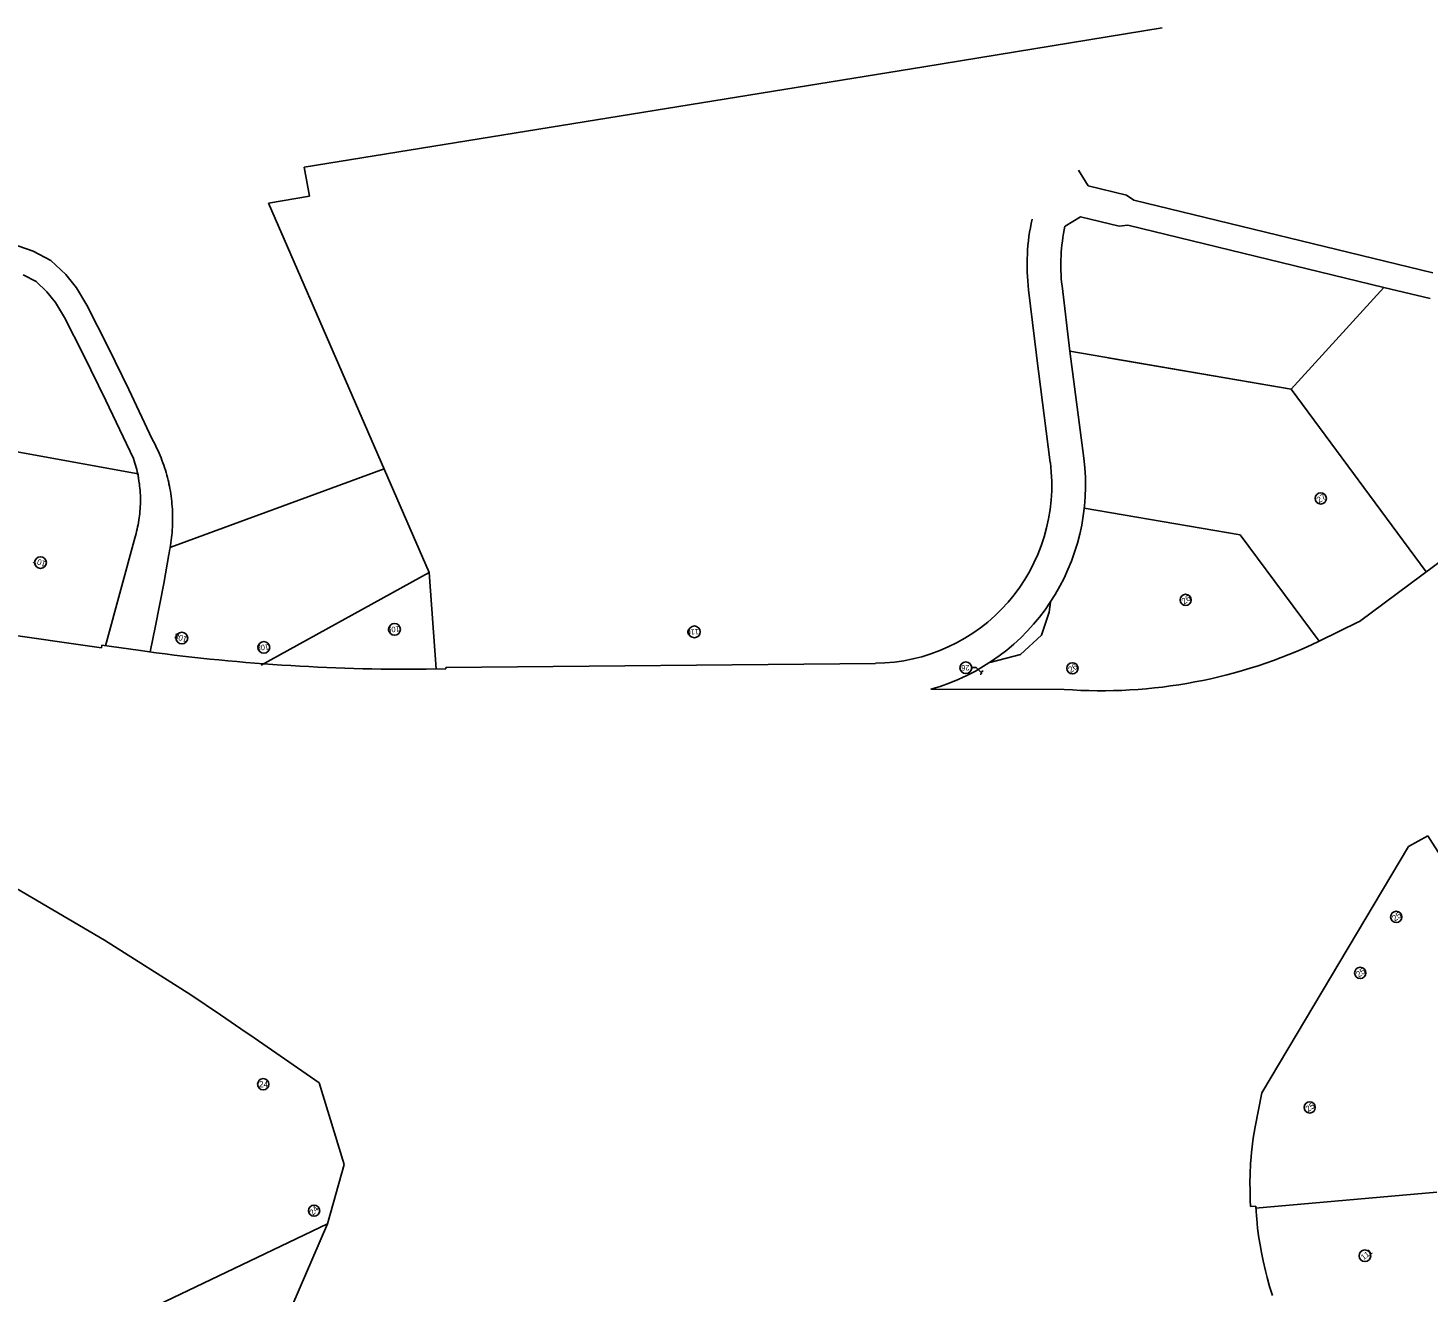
# Model space of a CAD drawing. Extents: x 1601085 to 1622464, y 1082944 to 1103437.
# Drawn here: x 1609043 to 1611786, y 1093415 to 1095892 of the extents above; entities that cross this region are included whole.
import ezdxf

# ---------------------------------------------------------------- set-up
doc = ezdxf.new("R2010")
doc.units = 0
for name, color, linetype in [('RD_EX_Bldg', 7, 'Continuous'), ('RD_EX_Fence_ChLk', 7, 'Continuous'), ('RD_EX_Fence_Other_txCode', 7, 'Continuous')]:
    doc.layers.add(name, color=color, linetype=linetype)

msp = doc.modelspace()

# ---------------------------------------------------------------- linework, layer by layer
at = {"layer": 'RD_EX_Bldg'}
for p, q in [((1611265, 1095892.2), (1610798, 1095816.2)), ((1610798, 1095816.2), (1609583.8, 1095619.4)), ((1609583.8, 1095619.4), (1609594, 1095562.3)), ((1609594, 1095562.3), (1609513.7, 1095549.1)), ((1609513.7, 1095549.1), (1609828.7, 1094825.3)), ((1611517.8, 1095184), (1611699.9, 1095383.8)), ((1611517.8, 1095184), (1611084.5, 1095258.7)), ((1611158.8, 1095245.9), (1611517.8, 1095184)), ((1611782.8, 1094826.5), (1611517.8, 1095184)), ((1608950.6, 1095073.9), (1609258.4, 1095018.5)), ((1609740.3, 1095028.3), (1609322.7, 1094874.7)), ((1609258.4, 1095018.5), (1609259.3, 1095007.2)), ((1611418.2, 1094898.6), (1611112.2, 1094951.4)), ((1611572.7, 1094690.3), (1611418.2, 1094898.6)), ((1609499.7, 1094643.2), (1609828.7, 1094825.3)), ((1609828.7, 1094825.3), (1609842.5, 1094635.9)), ((1611043.5, 1094747.3), (1611046.2, 1094767.1)), ((1611028.5, 1094702.2), (1611043.5, 1094747.3)), ((1610987.5, 1094664.5), (1611028.5, 1094702.2)), ((1610928, 1094649.2), (1610930.2, 1094649.3)), ((1610930.2, 1094649.3), (1610987.5, 1094664.5)), ((1611803.7, 1093610.9), (1611448.2, 1093579.2)), ((1609629.5, 1093548.3), (1609476.9, 1093475.5)), ((1609476.9, 1093475.5), (1609049.5, 1093271.6))]:
    msp.add_line(p, q, dxfattribs=at)
at = {"layer": 'RD_EX_Fence_ChLk'}
for p, q in [((1610892.5, 1094638.9), (1610900.5, 1094639)), ((1610900.5, 1094639), (1610911.4, 1094628.7))]:
    msp.add_line(p, q, dxfattribs=at)
for centre, radius in [((1611576, 1094970.1), 11), ((1609067.1, 1094844.5), 11.5), ((1611311.3, 1094771.4), 11), ((1609761, 1094713.6), 11.5), ((1609344.1, 1094696.4), 11.5), ((1610348.5, 1094708.7), 11.5), ((1609504.8, 1094678.2), 11.5), ((1610880.5, 1094638.3), 11.5), ((1611089.4, 1094637.3), 11), ((1611724, 1094150.1), 11), ((1611653.3, 1094040.3), 11), ((1609503.5, 1093822.1), 11), ((1611554.4, 1093776.6), 11), ((1609603.3, 1093574.3), 11), ((1611662.5, 1093485.9), 11.5)]:
    msp.add_circle(centre, radius, dxfattribs=at)
for centre, start, end in [((1610908.8, 1094628.4), 262.3337, 8.1916), ((1610913.9, 1094629.3), 82.3337, 188.1916)]:
    msp.add_arc(centre, 2.64, start, end, dxfattribs=at)
at = {"layer": 'RD_EX_Fence_Other_txCode'}
for p, q in [((1611651.7, 1094729.1), (1613041.3, 1095762)), ((1611120.3, 1095583.1), (1611101.6, 1095613.4)), ((1611195.6, 1095564.8), (1611120.3, 1095583.1)), ((1611209.7, 1095554.6), (1611195.6, 1095564.8)), ((1611795.7, 1095412), (1611209.7, 1095554.6)), ((1611105.4, 1095521.8), (1611074.9, 1095503.5)), ((1611180.7, 1095503.5), (1611105.4, 1095521.8)), ((1611197.9, 1095506), (1611180.7, 1095503.5)), ((1611699.9, 1095383.8), (1611197.9, 1095506)), ((1609053, 1095454.5), (1608977.9, 1095480.6)), ((1609087.6, 1095436.3), (1609053, 1095454.5)), ((1609116.6, 1095409.1), (1609087.6, 1095436.3)), ((1609033.1, 1095408.5), (1609058.4, 1095395.2)), ((1609137.7, 1095382.8), (1609116.6, 1095409.1)), ((1609058.4, 1095395.2), (1609079.8, 1095375.1)), ((1609157.9, 1095349.1), (1609137.7, 1095382.8)), ((1611019, 1095250.8), (1611003.6, 1095379)), ((1611084.5, 1095258.7), (1611069.1, 1095386.9)), ((1611699.9, 1095383.8), (1611790.4, 1095361.7)), ((1609079.8, 1095375.1), (1609096.5, 1095354.2)), ((1609096.5, 1095354.2), (1609114.1, 1095324.8)), ((1609114.1, 1095324.8), (1609151.5, 1095251.7)), ((1609200.3, 1095265.6), (1609157.9, 1095349.1)), ((1609151.5, 1095251.7), (1609195.4, 1095162.3)), ((1609240.5, 1095183.9), (1609200.3, 1095265.6)), ((1611046.1, 1095040.8), (1611019, 1095250.2)), ((1611111.6, 1095049.2), (1611084.5, 1095258.7)), ((1609195.4, 1095162.3), (1609249.4, 1095048.2)), ((1609286.1, 1095086.4), (1609240.5, 1095183.9)), ((1609252.5, 1094894.9), (1609194.8, 1094681.5)), ((1609308.8, 1094803.5), (1609318.4, 1094860.5)), ((1609292.4, 1094720.6), (1609308.8, 1094803.5)), ((1609282.3, 1094669.3), (1609292.4, 1094720.6)), ((1611650.3, 1094728.1), (1611572.7, 1094690.3)), ((1611651.7, 1094729.1), (1611650.3, 1094728.1)), ((1608893.4, 1094718.9), (1609186.6, 1094677.6)), ((1609186.6, 1094677.6), (1609187.3, 1094682.6)), ((1609187.3, 1094682.6), (1609258.6, 1094672.5)), ((1610703.3, 1094647), (1609861.5, 1094639)), ((1609861.5, 1094639), (1609861.5, 1094636)), ((1609861.5, 1094636), (1609822.9, 1094635.7)), ((1610811.6, 1094596.3), (1611073.4, 1094595.8)), ((1611786.2, 1094309), (1611748.2, 1094288)), ((1611748.2, 1094288), (1611460.9, 1093805.2)), ((1609020.4, 1094205.8), (1609192.7, 1094104.7)), ((1609192.7, 1094104.7), (1609361.6, 1093997.5)), ((1609361.6, 1093997.5), (1609419.8, 1093957.8)), ((1609419.8, 1093957.8), (1609470.3, 1093923.7)), ((1609470.3, 1093923.7), (1609477.3, 1093918.9)), ((1609477.3, 1093918.9), (1609613.3, 1093824.8)), ((1609613.3, 1093824.8), (1609662.5, 1093664.8)), ((1609662.5, 1093664.8), (1609629.5, 1093548.3)), ((1611438.6, 1093582.6), (1611448.6, 1093583)), ((1609629.5, 1093548.3), (1609542, 1093346.4))]:
    msp.add_line(p, q, dxfattribs=at)
for points in [[(1609286.1, 1095086.4), (1609288.5, 1095081.9), (1609290.9, 1095077.4), (1609293.1, 1095072.9), (1609295.3, 1095068.3), (1609297.5, 1095063.7), (1609299.5, 1095059), (1609301.5, 1095054.3), (1609303.4, 1095049.6), (1609305.2, 1095044.9), (1609307, 1095040.1), (1609308.7, 1095035.3), (1609310.3, 1095030.5), (1609311.8, 1095025.7), (1609313.3, 1095020.8), (1609314.7, 1095015.9), (1609316, 1095011), (1609317.2, 1095006.1), (1609318.3, 1095001.1), (1609318.8, 1094999), (1609319.8, 1094994.5), (1609320.7, 1094989.5), (1609321.6, 1094984.5), (1609322.4, 1094979.4), (1609323.1, 1094974.4), (1609323.8, 1094969.4), (1609324.4, 1094964.3), (1609324.8, 1094959.3), (1609325.3, 1094954.2), (1609325.6, 1094949.1), (1609325.8, 1094944.1), (1609326, 1094939), (1609326.1, 1094933.9), (1609326.1, 1094928.8), (1609326, 1094923.7), (1609325.9, 1094918.7), (1609325.7, 1094913.6), (1609325.4, 1094908.5), (1609325, 1094903.4), (1609324.5, 1094898.4), (1609323.9, 1094893.3), (1609323.3, 1094888.3), (1609322.6, 1094883.2), (1609321.8, 1094878.2), (1609321, 1094873.2), (1609320, 1094868.2), (1609319, 1094863.2), (1609318.4, 1094860.5)], [(1609249.4, 1095048.2), (1609250.8, 1095043.9), (1609252.2, 1095039.6), (1609253.4, 1095035.3), (1609254.6, 1095031), (1609255.7, 1095026.7), (1609256.8, 1095022.3), (1609257.7, 1095017.9), (1609258.6, 1095013.5), (1609259.4, 1095009.1), (1609260.1, 1095004.7), (1609260.7, 1095000.3), (1609260.9, 1094999), (1609261.4, 1094994.5), (1609261.9, 1094990.1), (1609262.3, 1094985.6), (1609262.6, 1094981.1), (1609262.8, 1094976.7), (1609262.9, 1094972.2), (1609263, 1094967.7), (1609263, 1094963.2), (1609262.9, 1094958.7), (1609262.7, 1094954.2), (1609262.4, 1094949.8), (1609262.1, 1094945.3), (1609261.6, 1094940.8), (1609261.1, 1094936.4), (1609260.6, 1094931.9), (1609259.9, 1094927.5), (1609259.2, 1094923.1), (1609258.4, 1094918.7), (1609257.5, 1094914.3), (1609256.5, 1094909.9), (1609255.4, 1094905.5), (1609254.3, 1094901.2), (1609253.1, 1094896.9), (1609252.5, 1094894.9)], [(1612209.8, 1093638.6), (1612197.8, 1093657.9), (1612172.2, 1093698.3), (1612144, 1093742.5), (1612115.5, 1093787.5), (1612088.3, 1093830.5), (1612061.2, 1093873.4), (1612033.2, 1093917.6), (1612005.8, 1093961.5), (1611978.4, 1094004.8), (1611950.5, 1094048.8), (1611922.6, 1094092.6), (1611895.6, 1094135.4), (1611868.8, 1094178), (1611841.9, 1094220.6), (1611814.8, 1094263.7), (1611786.2, 1094309)], [(1611460.9, 1093805.2), (1611447.2, 1093738.9), (1611443.6, 1093716.3), (1611440.2, 1093688.1), (1611439.4, 1093680.1), (1611438.3, 1093665.8), (1611437.4, 1093646.8), (1611437.2, 1093628.7), (1611437.4, 1093615.2), (1611438, 1093595.1), (1611438.6, 1093582.6)], [(1611448.6, 1093583), (1611448.6, 1093582.8), (1611450, 1093563.9), (1611450.5, 1093558.1), (1611452.4, 1093540.2), (1611454.9, 1093521.4), (1611457, 1093507.5), (1611459.9, 1093492.5), (1611463.3, 1093475.9), (1611467.5, 1093456.6), (1611470.8, 1093443.2), (1611475.9, 1093425.6), (1611481.7, 1093408.2)]]:
    msp.add_lwpolyline(points, dxfattribs=at)
for centre, radius, start, end in [((1611415.6, 1095428.2), 415, 167.5357, 186.8032), ((1611415.6, 1095428.2), 349, 167.5357, 186.8032), ((1610700, 1094996), 349, 270.5415, 7.3718), ((1610700, 1094996), 415, 285.6033, 7.3718), ((1609787.1, 1098425.2), 3789.7, 261.9834, 270.5415), ((1611145.1, 1095583.8), 990.6, 265.8491, 295.5724)]:
    msp.add_arc(centre, radius, start, end, dxfattribs=at)

# ---------------------------------------------------------------- texts
at = {"layer": 'RD_EX_Fence_ChLk'}
for s, height, rotation, p in [('27', 12, 35.0468, (1611572.9, 1094960.6)), ('107', 11.4, 160.7681, (1609078.9, 1094846.4)), ('26', 12, 35.0468, (1611308.2, 1094761.8)), ('108', 11.4, 160.7681, (1609355.9, 1094698.3)), ('109', 10.83, 182.696, (1609770.7, 1094719.5)), ('110', 10.83, 182.696, (1610357.2, 1094714.5)), ('108', 10.83, 182.696, (1609514.6, 1094684.1)), ('26', 10.83, 182.696, (1610887.5, 1094644.1)), ('26', 12, 35.0468, (1611086.2, 1094627.7)), ('25', 12, 35.0468, (1611720.9, 1094140.6)), ('25', 12, 35.0468, (1611650.2, 1094030.8)), ('24', 12, 0.7452, (1609495.5, 1093816)), ('25', 12, 35.0468, (1611551.2, 1093767.1)), ('24', 12, 48.1297, (1609601.3, 1093564)), ('111', 10.83, 37.2466, (1611659.9, 1093477.2))]:
    msp.add_text(s, height=height, rotation=rotation, dxfattribs=at).set_placement(p)

doc.saveas('drawing.dxf')
